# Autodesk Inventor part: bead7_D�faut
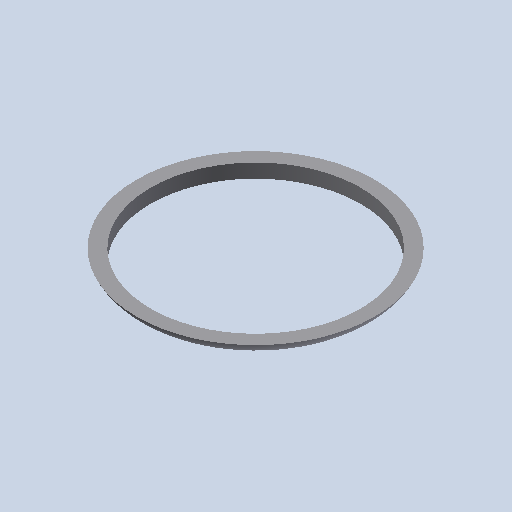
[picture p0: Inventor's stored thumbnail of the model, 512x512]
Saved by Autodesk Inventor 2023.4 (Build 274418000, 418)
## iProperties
Created: 2011-01
Part Number: bead7_D�faut
Document SubType Name: Modeling
Designer: eric
Density: 1 g/cm^3
Mass: 0.244938 g
Surface Area: 6.80389 cm^2
Volume: 0.244938 cm^3
Material: Générique
Appearance: Par défaut
Author: eric
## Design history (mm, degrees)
feature "Base1"
node "Corps solides"
node "Corps surfaciques"
node "Solide1"
